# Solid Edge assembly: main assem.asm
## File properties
Author: Robert a Rhodes jr
Template: Normal.asm
Last saved by: CADCIM
Revision: 15
Application: Solid Edge
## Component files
master rod.par
piston.par
piston pin.par
arti subassm.asm
piston pin plug.par
piston ring.par
master rod bearing.par
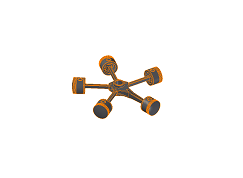
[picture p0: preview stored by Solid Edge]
